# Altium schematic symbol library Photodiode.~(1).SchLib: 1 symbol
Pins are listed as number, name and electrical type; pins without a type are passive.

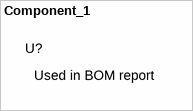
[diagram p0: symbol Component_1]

## Component_1
designator U?, comment Used in BOM report
SymbolVersion: use current date i.e. 2008-05-20; SymbolCreator: Use LDAP id; CompType: Used in some BOM reports.  Useful for finding later.; U/M: EA, IN, or GM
